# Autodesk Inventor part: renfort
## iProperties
Created: 2011-01
Part Number: renfort
Document SubType Name: Modeling
Designer: eric
Density: 1 g/cm^3
Mass: 1.89109 g
Surface Area: 27.7168 cm^2
Volume: 1.89109 cm^3
Author: eric
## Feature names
1. Base1
